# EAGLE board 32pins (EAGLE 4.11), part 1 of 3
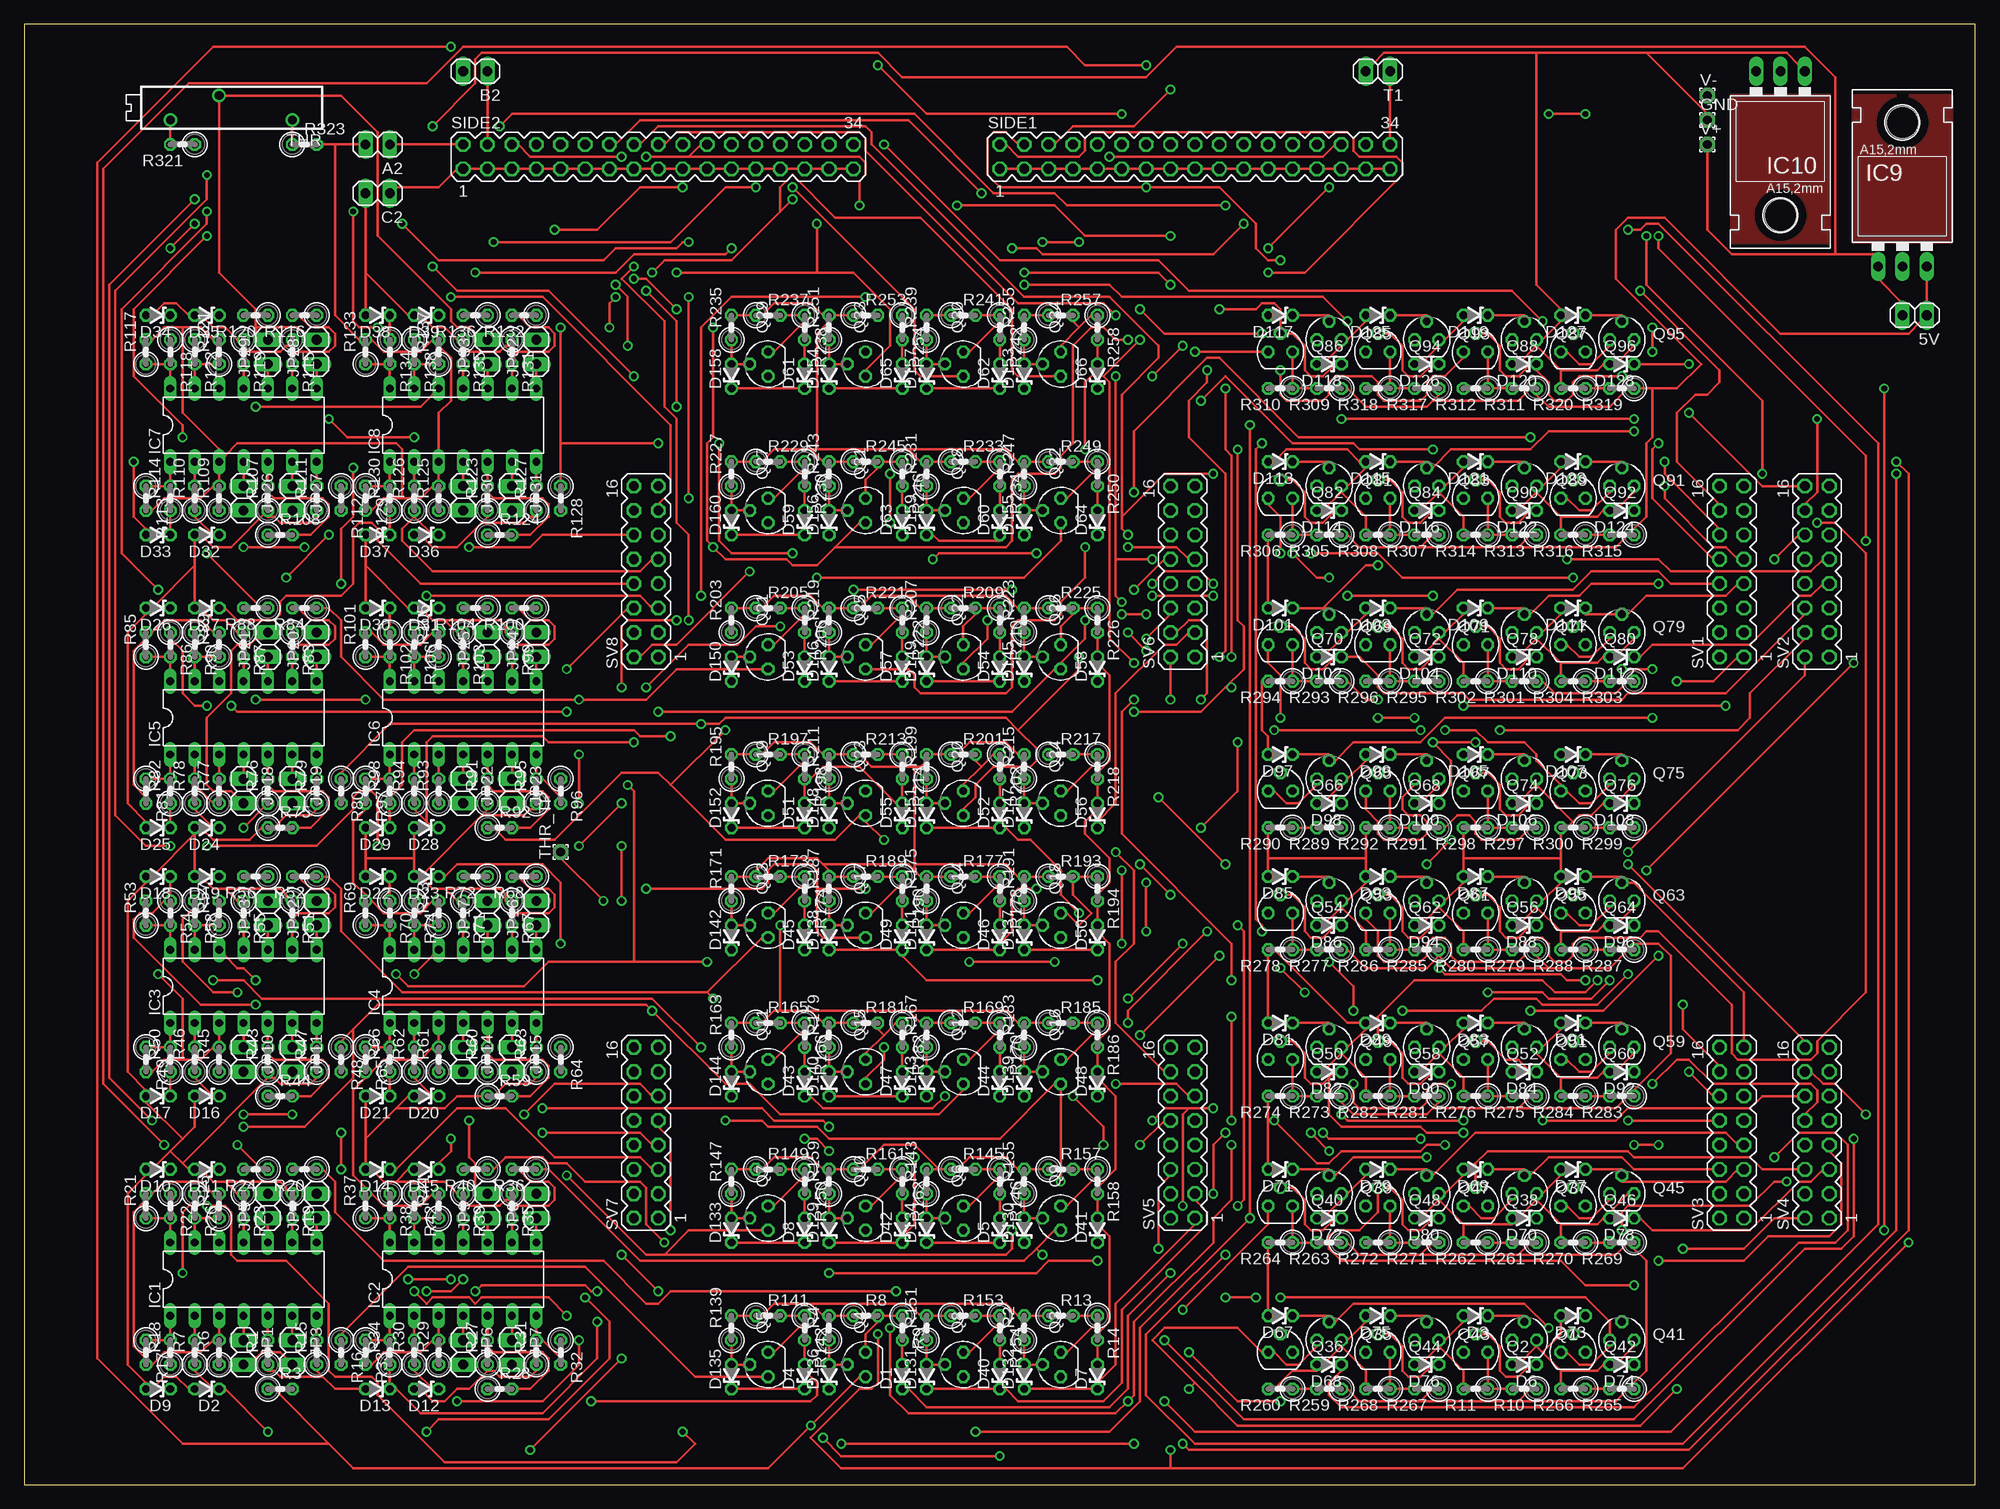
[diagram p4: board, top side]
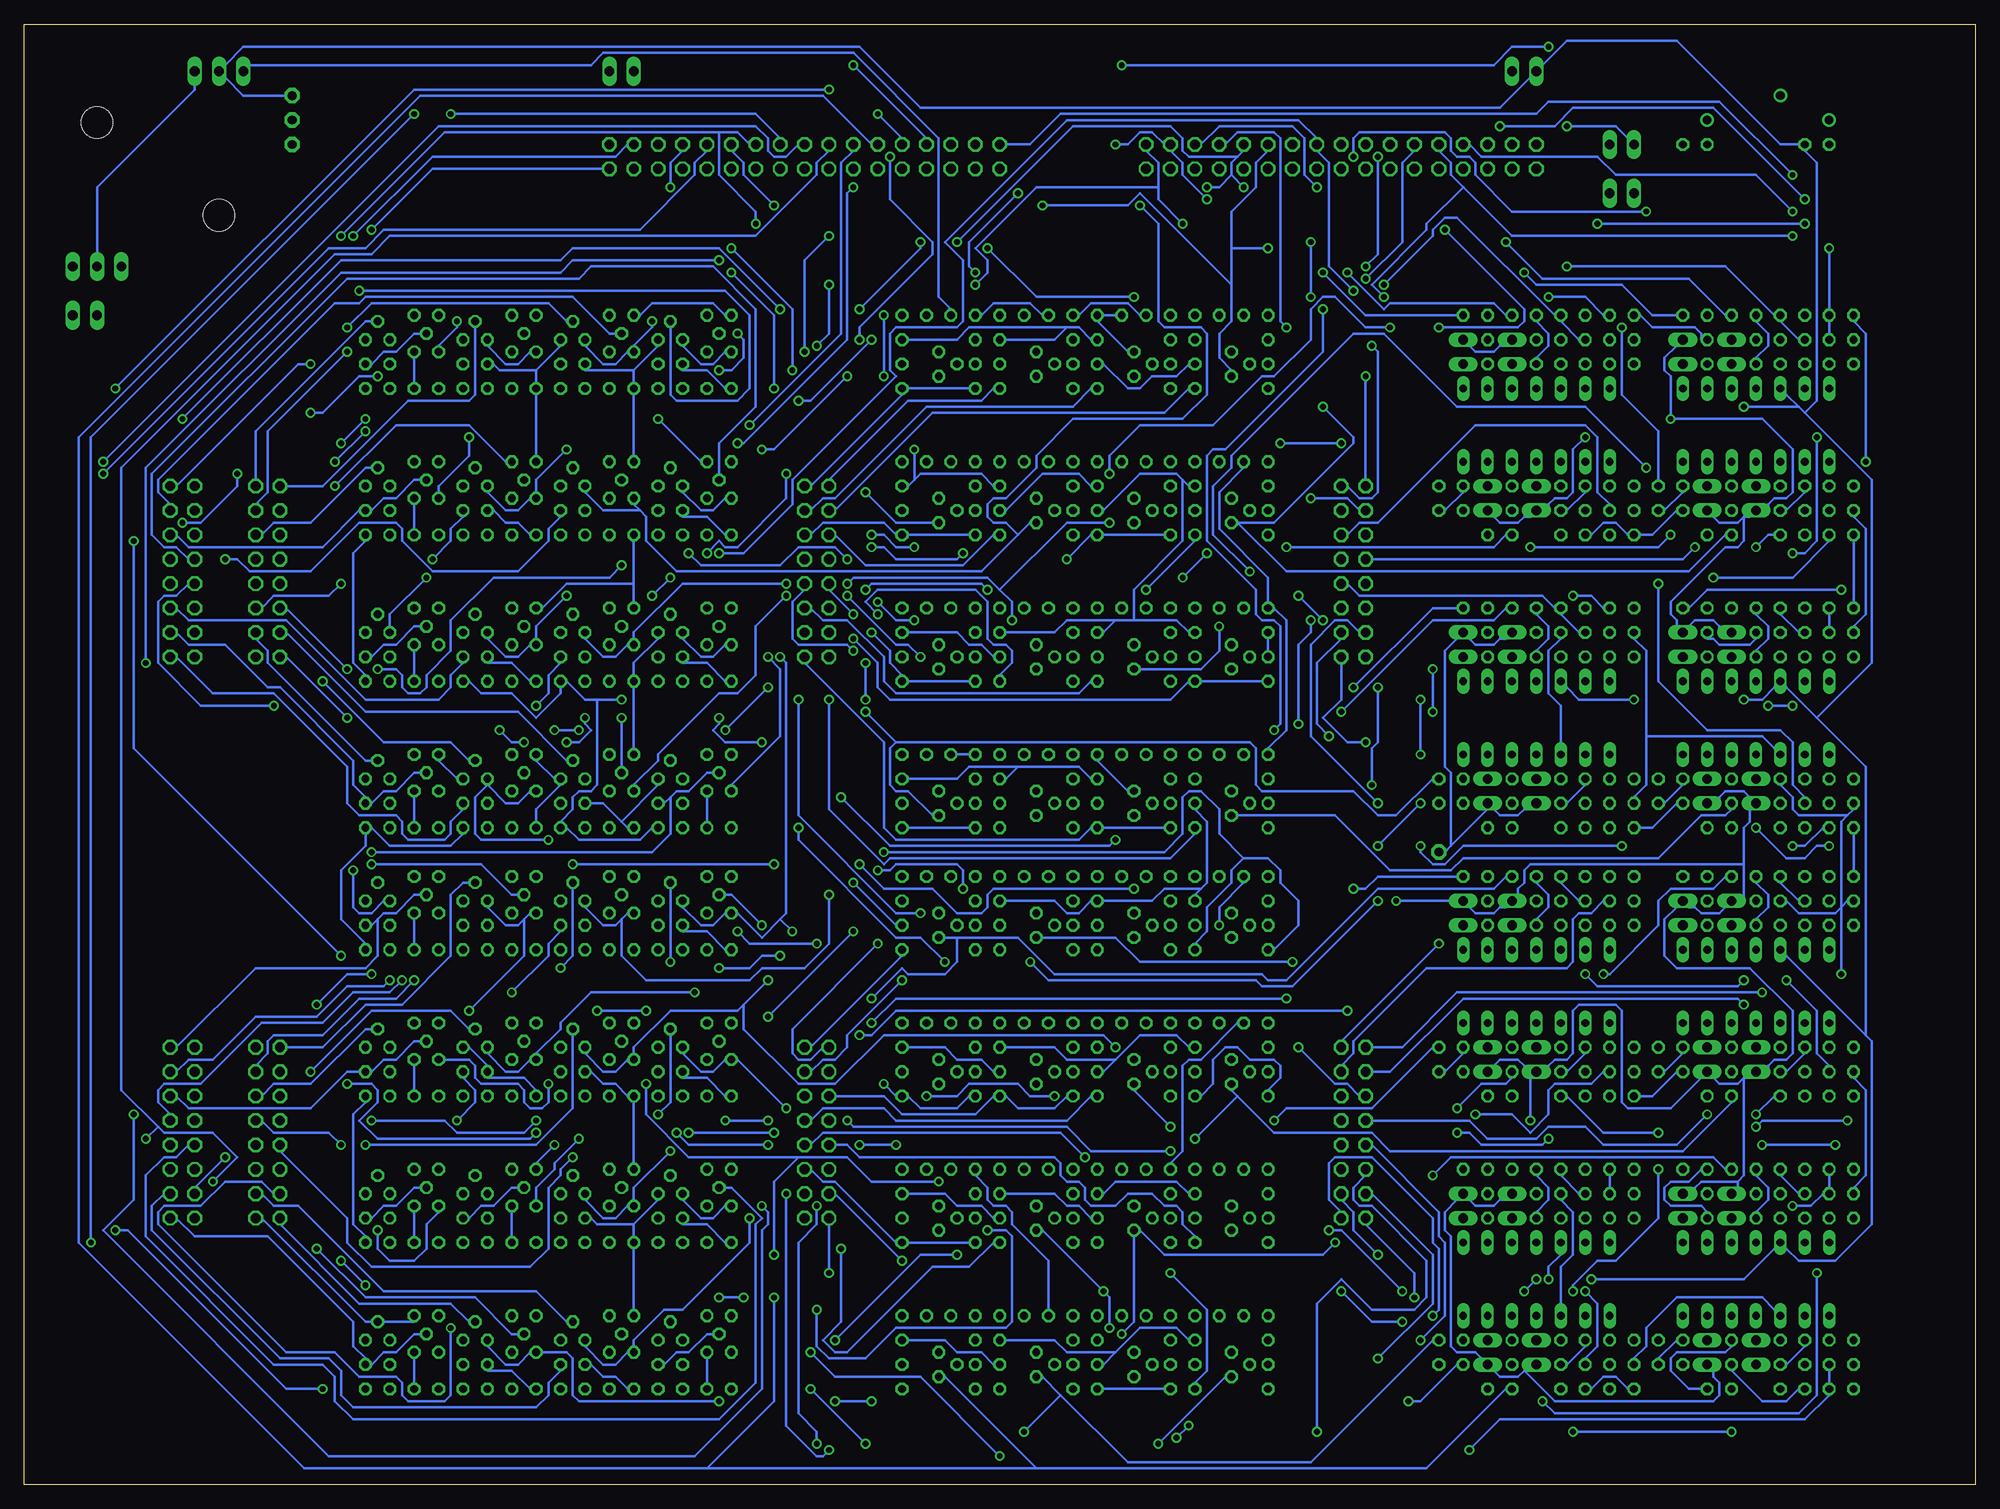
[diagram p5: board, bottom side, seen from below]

Size 203.18 x 152.07 mm. Coordinates in mm from the lower left corner, seen from the top.
Outline: 0,0 203.18,0 203.18,152.07 0,152.07 0,0
Copper layers (1*16): Top 0.035mm / dielectric 1.5mm / Bottom 0.035mm
Design rules "default": minimum track width 10mil, minimum drill 24mil, track to track 8mil, track to pad 8mil, pad to pad 8mil, via to via 8mil, smd to smd 8mil, copper to edge 40mil, drill to drill 8mil, minimum pad ring 10mil, minimum via ring 8mil, stop-mask expansion 4mil, vias tented up to drill 0mil, thermal gap 10mil

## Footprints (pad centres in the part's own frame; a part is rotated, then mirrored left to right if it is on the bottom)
1X02 = drill 1.016 long: 1 -1.27,0; 2 1.27,0
ZDIO-2.5 = drill 0.813 octagon: A 1.27,0; C -1.27,0
1,6/0,9 = drill 0.914 pad 1.6 octagon: 1 0,0
DIL14 = drill 0.813 long: 1 -7.62,-3.81; 2 -5.08,-3.81; 3 -2.54,-3.81; 4 0,-3.81; 5 2.54,-3.81; 6 5.08,-3.81; 7 7.62,-3.81; 8 7.62,3.81; 9 5.08,3.81; 10 2.54,3.81; 11 0,3.81; 12 -2.54,3.81; 13 -5.08,3.81; 14 -7.62,3.81
78XXL = drill 1.016 long: GND 0,-3.81; IN -2.54,-3.81; OUT 2.54,-3.81 | hole 3.302: 0,11.176
79XXL = drill 1.016 long: GND -2.54,-3.81; IN 0,-3.81; OUT 2.54,-3.81 | hole 3.302: 0,11.176
SOT54E = drill 0.813 octagon: D -1.27,0; G 0,1.905; S 1.27,0
0207/2V = drill 0.813 octagon: 1 -1.27,0; 2 1.27,0
MA17-2 = drill 1.016 octagon: 1 -20.32,-1.27; 2 -20.32,1.27; 3 -17.78,-1.27; 4 -17.78,1.27; 5 -15.24,-1.27; 6 -15.24,1.27; 7 -12.7,-1.27; 8 -12.7,1.27; 9 -10.16,-1.27; 10 -10.16,1.27; 11 -7.62,-1.27; 12 -7.62,1.27; 13 -5.08,-1.27; 14 -5.08,1.27; 15 -2.54,-1.27; 16 -2.54,1.27; 17 0,-1.27; 18 0,1.27; 19 2.54,-1.27; 20 2.54,1.27; 21 5.08,-1.27; 22 5.08,1.27; 23 7.62,-1.27; 24 7.62,1.27; 25 10.16,-1.27; 26 10.16,1.27; 27 12.7,-1.27; 28 12.7,1.27; 29 15.24,-1.27; 30 15.24,1.27; 31 17.78,-1.27; 32 17.78,1.27; 33 20.32,-1.27; 34 20.32,1.27
MA08-2 = drill 1.016 octagon: 1 -8.89,-1.27; 2 -8.89,1.27; 3 -6.35,-1.27; 4 -6.35,1.27; 5 -3.81,-1.27; 6 -3.81,1.27; 7 -1.27,-1.27; 8 -1.27,1.27; 9 1.27,-1.27; 10 1.27,1.27; 11 3.81,-1.27; 12 3.81,1.27; 13 6.35,-1.27; 14 6.35,1.27; 15 8.89,-1.27; 16 8.89,1.27
RTRIMT18 = drill 0.9 round: 1 -7.62,1.27; 2 0,-1.27; 3 5.08,1.27

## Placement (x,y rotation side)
5V  [1X02]  196.84,121.75 180 top
A2  [1X02]  36.82,139.53 180 top
B2  [1X02]  46.98,147.16 180 top
C2  [1X02]  36.82,134.46 180 top
D1  1N5229B  [ZDIO-2.5]  91.44,11.27 90 top
D2  1N5229B  [ZDIO-2.5]  19.05,10 180 top
D3  1N5229B  [ZDIO-2.5]  151.12,17.62 180 top
D4  1N5229B  [ZDIO-2.5]  81.28,11.27 90 top
D5  1N5229B  [ZDIO-2.5]  101.59,26.51 90 top
D6  1N5229B  [ZDIO-2.5]  156.21,12.54 180 top
D7  1N5229B  [ZDIO-2.5]  111.76,11.27 90 top
D8  1N5229B  [ZDIO-2.5]  81.28,26.51 90 top
D9  1N5229B  [ZDIO-2.5]  13.96,10 180 top
D10  1N5229B  [ZDIO-2.5]  13.96,32.86 180 top
D11  1N5229B  [ZDIO-2.5]  19.05,32.86 180 top
D12  1N5229B  [ZDIO-2.5]  41.9,10 180 top
D13  1N5229B  [ZDIO-2.5]  36.82,10 180 top
D14  1N5229B  [ZDIO-2.5]  36.82,32.86 180 top
D15  1N5229B  [ZDIO-2.5]  41.9,32.86 180 top
D16  1N5229B  [ZDIO-2.5]  19.05,40.48 180 top
D17  1N5229B  [ZDIO-2.5]  13.96,40.48 180 top
D18  1N5229B  [ZDIO-2.5]  13.96,63.34 180 top
D19  1N5229B  [ZDIO-2.5]  19.05,63.34 180 top
D20  1N5229B  [ZDIO-2.5]  41.9,40.48 180 top
D21  1N5229B  [ZDIO-2.5]  36.82,40.48 180 top
D22  1N5229B  [ZDIO-2.5]  36.82,63.34 180 top
D23  1N5229B  [ZDIO-2.5]  41.9,63.34 180 top
D24  1N5229B  [ZDIO-2.5]  19.05,68.41 180 top
D25  1N5229B  [ZDIO-2.5]  13.96,68.41 180 top
D26  1N5229B  [ZDIO-2.5]  13.96,91.27 180 top
D27  1N5229B  [ZDIO-2.5]  19.05,91.27 180 top
D28  1N5229B  [ZDIO-2.5]  41.9,68.41 180 top
D29  1N5229B  [ZDIO-2.5]  36.82,68.41 180 top
D30  1N5229B  [ZDIO-2.5]  36.82,91.27 180 top
D31  1N5229B  [ZDIO-2.5]  41.9,91.27 180 top
D32  1N5229B  [ZDIO-2.5]  19.05,98.89 180 top
D33  1N5229B  [ZDIO-2.5]  13.96,98.89 180 top
D34  1N5229B  [ZDIO-2.5]  13.96,121.75 180 top
D35  1N5229B  [ZDIO-2.5]  19.05,121.75 180 top
D36  1N5229B  [ZDIO-2.5]  41.9,98.89 180 top
D37  1N5229B  [ZDIO-2.5]  36.82,98.89 180 top
D38  1N5229B  [ZDIO-2.5]  36.82,121.75 180 top
D39  1N5229B  [ZDIO-2.5]  41.9,121.75 180 top
D40  1N5229B  [ZDIO-2.5]  101.59,11.27 90 top
D41  1N5229B  [ZDIO-2.5]  111.76,26.51 90 top
D42  1N5229B  [ZDIO-2.5]  91.44,26.51 90 top
D43  1N5229B  [ZDIO-2.5]  81.28,41.74 90 top
D44  1N5229B  [ZDIO-2.5]  101.59,41.74 90 top
D45  1N5229B  [ZDIO-2.5]  81.28,56.98 90 top
D46  1N5229B  [ZDIO-2.5]  101.59,56.98 90 top
D47  1N5229B  [ZDIO-2.5]  91.44,41.74 90 top
D48  1N5229B  [ZDIO-2.5]  111.76,41.74 90 top
D49  1N5229B  [ZDIO-2.5]  91.44,56.98 90 top
D50  1N5229B  [ZDIO-2.5]  111.76,56.98 90 top
D51  1N5229B  [ZDIO-2.5]  81.28,69.68 90 top
D52  1N5229B  [ZDIO-2.5]  101.59,69.68 90 top
D53  1N5229B  [ZDIO-2.5]  81.28,84.92 90 top
D54  1N5229B  [ZDIO-2.5]  101.59,84.92 90 top
D55  1N5229B  [ZDIO-2.5]  91.44,69.68 90 top
D56  1N5229B  [ZDIO-2.5]  111.76,69.68 90 top
D57  1N5229B  [ZDIO-2.5]  91.44,84.92 90 top
D58  1N5229B  [ZDIO-2.5]  111.76,84.92 90 top
D59  1N5229B  [ZDIO-2.5]  81.28,100.16 90 top
D60  1N5229B  [ZDIO-2.5]  101.59,100.16 90 top
D61  1N5229B  [ZDIO-2.5]  81.28,115.4 90 top
D62  1N5229B  [ZDIO-2.5]  101.59,115.4 90 top
D63  1N5229B  [ZDIO-2.5]  91.44,100.16 90 top
D64  1N5229B  [ZDIO-2.5]  111.76,100.16 90 top
D65  1N5229B  [ZDIO-2.5]  91.44,115.4 90 top
D66  1N5229B  [ZDIO-2.5]  111.76,115.4 90 top
D67  1N5229B  [ZDIO-2.5]  130.81,17.62 180 top
D68  1N5229B  [ZDIO-2.5]  135.88,12.54 180 top
D69  1N5229B  [ZDIO-2.5]  151.12,32.86 180 top
D70  1N5229B  [ZDIO-2.5]  156.21,27.78 180 top
D71  1N5229B  [ZDIO-2.5]  130.81,32.86 180 top
D72  1N5229B  [ZDIO-2.5]  135.88,27.78 180 top
D73  1N5229B  [ZDIO-2.5]  161.28,17.62 180 top
D74  1N5229B  [ZDIO-2.5]  166.37,12.54 180 top
D75  1N5229B  [ZDIO-2.5]  140.97,17.62 180 top
D76  1N5229B  [ZDIO-2.5]  146.05,12.54 180 top
D77  1N5229B  [ZDIO-2.5]  161.28,32.86 180 top
D78  1N5229B  [ZDIO-2.5]  166.37,27.78 180 top
D79  1N5229B  [ZDIO-2.5]  140.97,32.86 180 top
D80  1N5229B  [ZDIO-2.5]  146.05,27.78 180 top
D81  1N5229B  [ZDIO-2.5]  130.81,48.09 180 top
D82  1N5229B  [ZDIO-2.5]  135.88,43.02 180 top
D83  1N5229B  [ZDIO-2.5]  151.12,48.09 180 top
D84  1N5229B  [ZDIO-2.5]  156.21,43.02 180 top
D85  1N5229B  [ZDIO-2.5]  130.81,63.34 180 top
D86  1N5229B  [ZDIO-2.5]  135.88,58.26 180 top
D87  1N5229B  [ZDIO-2.5]  151.12,63.34 180 top
D88  1N5229B  [ZDIO-2.5]  156.21,58.26 180 top
D89  1N5229B  [ZDIO-2.5]  140.97,48.09 180 top
D90  1N5229B  [ZDIO-2.5]  146.05,43.02 180 top
D91  1N5229B  [ZDIO-2.5]  161.28,48.09 180 top
D92  1N5229B  [ZDIO-2.5]  166.37,43.02 180 top
D93  1N5229B  [ZDIO-2.5]  140.97,63.34 180 top
D94  1N5229B  [ZDIO-2.5]  146.05,58.26 180 top
D95  1N5229B  [ZDIO-2.5]  161.28,63.34 180 top
D96  1N5229B  [ZDIO-2.5]  166.37,58.26 180 top
D97  1N5229B  [ZDIO-2.5]  130.81,76.03 180 top
D98  1N5229B  [ZDIO-2.5]  135.88,70.95 180 top
D99  1N5229B  [ZDIO-2.5]  140.97,76.03 180 top
D100  1N5229B  [ZDIO-2.5]  146.05,70.95 180 top
D101  1N5229B  [ZDIO-2.5]  130.81,91.27 180 top
D102  1N5229B  [ZDIO-2.5]  135.88,86.19 180 top
D103  1N5229B  [ZDIO-2.5]  140.97,91.27 180 top
D104  1N5229B  [ZDIO-2.5]  146.05,86.19 180 top
D105  1N5229B  [ZDIO-2.5]  151.12,76.03 180 top
D106  1N5229B  [ZDIO-2.5]  156.21,70.95 180 top
D107  1N5229B  [ZDIO-2.5]  161.28,76.03 180 top
D108  1N5229B  [ZDIO-2.5]  166.37,70.95 180 top
D109  1N5229B  [ZDIO-2.5]  151.12,91.27 180 top
D110  1N5229B  [ZDIO-2.5]  156.21,86.19 180 top
D111  1N5229B  [ZDIO-2.5]  161.28,91.27 180 top
D112  1N5229B  [ZDIO-2.5]  166.37,86.19 180 top
D113  1N5229B  [ZDIO-2.5]  130.81,106.52 180 top
D114  1N5229B  [ZDIO-2.5]  135.88,101.43 180 top
D115  1N5229B  [ZDIO-2.5]  140.97,106.52 180 top
D116  1N5229B  [ZDIO-2.5]  146.05,101.43 180 top
D117  1N5229B  [ZDIO-2.5]  130.81,121.75 180 top
D118  1N5229B  [ZDIO-2.5]  135.88,116.67 180 top
D119  1N5229B  [ZDIO-2.5]  151.12,121.75 180 top
D120  1N5229B  [ZDIO-2.5]  156.21,116.67 180 top
D121  1N5229B  [ZDIO-2.5]  151.12,106.52 180 top
D122  1N5229B  [ZDIO-2.5]  156.21,101.43 180 top
D123  1N5229B  [ZDIO-2.5]  161.28,106.52 180 top
D124  1N5229B  [ZDIO-2.5]  166.37,101.43 180 top
D125  1N5229B  [ZDIO-2.5]  140.97,121.75 180 top
D126  1N5229B  [ZDIO-2.5]  146.05,116.67 180 top
D127  1N5229B  [ZDIO-2.5]  161.28,121.75 180 top
D128  1N5229B  [ZDIO-2.5]  166.37,116.67 180 top
D129  1N5225/3V  [ZDIO-2.5]  83.81,26.51 90 top
D130  1N5225/3V  [ZDIO-2.5]  104.14,26.51 90 top
D131  1N5225/3V  [ZDIO-2.5]  93.98,11.27 90 top
D132  1N5225/3V  [ZDIO-2.5]  104.14,11.27 90 top
D133  1N5225/3V  [ZDIO-2.5]  73.66,26.51 90 top
D134  1N5225/3V  [ZDIO-2.5]  93.98,26.51 90 top
D135  1N5225/3V  [ZDIO-2.5]  73.66,11.27 90 top
D136  1N5225/3V  [ZDIO-2.5]  83.81,11.27 90 top
D137  1N5225/3V  [ZDIO-2.5]  104.14,56.98 90 top
D138  1N5225/3V  [ZDIO-2.5]  83.81,56.98 90 top
D139  1N5225/3V  [ZDIO-2.5]  104.14,41.74 90 top
D140  1N5225/3V  [ZDIO-2.5]  83.81,41.74 90 top
D141  1N5225/3V  [ZDIO-2.5]  93.98,56.98 90 top
D142  1N5225/3V  [ZDIO-2.5]  73.66,56.98 90 top
D143  1N5225/3V  [ZDIO-2.5]  93.98,41.74 90 top
D144  1N5225/3V  [ZDIO-2.5]  73.66,41.74 90 top
D145  1N5225/3V  [ZDIO-2.5]  104.14,84.92 90 top
D146  1N5225/3V  [ZDIO-2.5]  83.81,84.92 90 top
D147  1N5225/3V  [ZDIO-2.5]  104.14,69.68 90 top
D148  1N5225/3V  [ZDIO-2.5]  83.81,69.68 90 top
D149  1N5225/3V  [ZDIO-2.5]  93.98,84.92 90 top
D150  1N5225/3V  [ZDIO-2.5]  73.66,84.92 90 top
D151  1N5225/3V  [ZDIO-2.5]  93.98,69.68 90 top
D152  1N5225/3V  [ZDIO-2.5]  73.66,69.68 90 top
D153  1N5225/3V  [ZDIO-2.5]  104.14,115.4 90 top
D154  1N5225/3V  [ZDIO-2.5]  83.81,115.4 90 top
D155  1N5225/3V  [ZDIO-2.5]  104.14,100.16 90 top
D156  1N5225/3V  [ZDIO-2.5]  83.81,100.16 90 top
D157  1N5225/3V  [ZDIO-2.5]  93.98,115.4 90 top
D158  1N5225/3V  [ZDIO-2.5]  73.66,115.4 90 top
D159  1N5225/3V  [ZDIO-2.5]  93.98,100.16 90 top
D160  1N5225/3V  [ZDIO-2.5]  73.66,100.16 90 top
GND  [1,6/0,9]  175.25,142.08 0 top
IC1  LM139N  [DIL14]  22.86,21.43 0 top
IC2  LM139N  [DIL14]  45.71,21.43 0 top
IC3  LM139N  [DIL14]  22.86,51.91 0 top
IC4  LM139N  [DIL14]  45.71,51.91 0 top
IC5  LM139N  [DIL14]  22.86,79.84 0 top
IC6  LM139N  [DIL14]  45.71,79.84 0 top
IC7  LM139N  [DIL14]  22.86,110.32 0 top
IC8  LM139N  [DIL14]  45.71,110.32 0 top
IC9  [78XXL]  195.58,130.65 0 top
IC10  [79XXL]  182.88,143.34 180 top
JP1  [1X02]  22.86,13.81 270 top
JP3  [1X02]  27.94,13.81 270 top
JP4  [1X02]  30.48,29.05 90 top
JP5  [1X02]  25.39,29.05 90 top
JP6  [1X02]  45.71,13.81 270 top
JP7  [1X02]  50.79,13.81 270 top
JP8  [1X02]  53.34,29.05 90 top
JP9  [1X02]  48.25,29.05 90 top
JP10  [1X02]  22.86,44.29 270 top
JP11  [1X02]  27.94,44.29 270 top
JP12  [1X02]  30.48,59.52 90 top
JP13  [1X02]  25.39,59.52 90 top
JP14  [1X02]  45.71,44.29 270 top
JP15  [1X02]  50.79,44.29 270 top
JP16  [1X02]  53.34,59.52 90 top
JP17  [1X02]  48.25,59.52 90 top
JP18  [1X02]  22.86,72.22 270 top
JP19  [1X02]  27.94,72.22 270 top
JP20  [1X02]  30.48,87.46 90 top
JP21  [1X02]  25.39,87.46 90 top
JP22  [1X02]  45.71,72.22 270 top
JP23  [1X02]  50.79,72.22 270 top
JP24  [1X02]  53.34,87.46 90 top
JP25  [1X02]  48.25,87.46 90 top
JP26  [1X02]  22.86,102.7 270 top
JP27  [1X02]  27.94,102.7 270 top
JP28  [1X02]  30.48,117.94 90 top
JP29  [1X02]  25.39,117.94 90 top
JP30  [1X02]  45.71,102.7 270 top
JP31  [1X02]  50.79,102.7 270 top
JP32  [1X02]  53.34,117.94 90 top
JP33  [1X02]  48.25,117.94 90 top
Q1  BS170  [SOT54E]  156.21,15.08 0 top
Q2  BS250  [SOT54E]  151.12,13.81 0 top
Q3  BS170  [SOT54E]  107.95,12.54 90 top
Q4  BS170  [SOT54E]  87.62,12.54 90 top
Q5  BS170  [SOT54E]  77.47,12.54 90 top
Q6  BS170  [SOT54E]  97.79,27.78 90 top
Q7  BS170  [SOT54E]  77.47,27.78 90 top
Q8  BS170  [SOT54E]  97.79,12.54 90 top
Q9  BS170  [SOT54E]  107.95,27.78 90 top
Q10  BS170  [SOT54E]  87.62,27.78 90 top
Q11  BS170  [SOT54E]  77.47,43.02 90 top
Q12  BS170  [SOT54E]  97.79,43.02 90 top
Q13  BS170  [SOT54E]  77.47,58.26 90 top
Q14  BS170  [SOT54E]  97.79,58.26 90 top
Q15  BS170  [SOT54E]  87.62,43.02 90 top
Q16  BS170  [SOT54E]  107.95,43.02 90 top
Q17  BS170  [SOT54E]  87.62,58.26 90 top
Q18  BS170  [SOT54E]  107.95,58.26 90 top
Q19  BS170  [SOT54E]  77.47,70.95 90 top
Q20  BS170  [SOT54E]  97.79,70.95 90 top
Q21  BS170  [SOT54E]  77.47,86.19 90 top
Q22  BS170  [SOT54E]  97.79,86.19 90 top
Q23  BS170  [SOT54E]  87.62,70.95 90 top
Q24  BS170  [SOT54E]  107.95,70.95 90 top
Q25  BS170  [SOT54E]  87.62,86.19 90 top
Q26  BS170  [SOT54E]  107.95,86.19 90 top
Q27  BS170  [SOT54E]  77.47,101.43 90 top
Q28  BS170  [SOT54E]  97.79,101.43 90 top
Q29  BS170  [SOT54E]  77.47,116.67 90 top
Q30  BS170  [SOT54E]  97.79,116.67 90 top
Q31  BS170  [SOT54E]  87.62,101.43 90 top
Q32  BS170  [SOT54E]  107.95,101.43 90 top
Q33  BS170  [SOT54E]  87.62,116.67 90 top
Q34  BS170  [SOT54E]  107.95,116.67 90 top
Q35  BS170  [SOT54E]  135.88,15.08 0 top
Q36  BS250  [SOT54E]  130.81,13.81 0 top
Q37  BS170  [SOT54E]  156.21,30.32 0 top
Q38  BS250  [SOT54E]  151.12,29.05 0 top
Q39  BS170  [SOT54E]  135.88,30.32 0 top
Q40  BS250  [SOT54E]  130.81,29.05 0 top
Q41  BS170  [SOT54E]  166.37,15.08 0 top
Q42  BS250  [SOT54E]  161.28,13.81 0 top
Q43  BS170  [SOT54E]  146.05,15.08 0 top
Q44  BS250  [SOT54E]  140.97,13.81 0 top
Q45  BS170  [SOT54E]  166.37,30.32 0 top
Q46  BS250  [SOT54E]  161.28,29.05 0 top
Q47  BS170  [SOT54E]  146.05,30.32 0 top
Q48  BS250  [SOT54E]  140.97,29.05 0 top
Q49  BS170  [SOT54E]  135.88,45.55 0 top
Q50  BS250  [SOT54E]  130.81,44.29 0 top
Q51  BS170  [SOT54E]  156.21,45.55 0 top
Q52  BS250  [SOT54E]  151.12,44.29 0 top
Q53  BS170  [SOT54E]  135.88,60.8 0 top
Q54  BS250  [SOT54E]  130.81,59.52 0 top
Q55  BS170  [SOT54E]  156.21,60.8 0 top
Q56  BS250  [SOT54E]  151.12,59.52 0 top
Q57  BS170  [SOT54E]  146.05,45.55 0 top
Q58  BS250  [SOT54E]  140.97,44.29 0 top
Q59  BS170  [SOT54E]  166.37,45.55 0 top
Q60  BS250  [SOT54E]  161.28,44.29 0 top
Q61  BS170  [SOT54E]  146.05,60.8 0 top
Q62  BS250  [SOT54E]  140.97,59.52 0 top
Q63  BS170  [SOT54E]  166.37,60.8 0 top
Q64  BS250  [SOT54E]  161.28,59.52 0 top
Q65  BS170  [SOT54E]  135.88,73.49 0 top
Q66  BS250  [SOT54E]  130.81,72.22 0 top
Q67  BS170  [SOT54E]  146.05,73.49 0 top
Q68  BS250  [SOT54E]  140.97,72.22 0 top
Q69  BS170  [SOT54E]  135.88,88.73 0 top
Q70  BS250  [SOT54E]  130.81,87.46 0 top
Q71  BS170  [SOT54E]  146.05,88.73 0 top
Q72  BS250  [SOT54E]  140.97,87.46 0 top
Q73  BS170  [SOT54E]  156.21,73.49 0 top
Q74  BS250  [SOT54E]  151.12,72.22 0 top
Q75  BS170  [SOT54E]  166.37,73.49 0 top
Q76  BS250  [SOT54E]  161.28,72.22 0 top
Q77  BS170  [SOT54E]  156.21,88.73 0 top
Q78  BS250  [SOT54E]  151.12,87.46 0 top
Q79  BS170  [SOT54E]  166.37,88.73 0 top
Q80  BS250  [SOT54E]  161.28,87.46 0 top
Q81  BS170  [SOT54E]  135.88,103.97 0 top
Q82  BS250  [SOT54E]  130.81,102.7 0 top
Q83  BS170  [SOT54E]  146.05,103.97 0 top
Q84  BS250  [SOT54E]  140.97,102.7 0 top
Q85  BS170  [SOT54E]  135.88,119.21 0 top
Q86  BS250  [SOT54E]  130.81,117.94 0 top
Q87  BS170  [SOT54E]  156.21,119.21 0 top
Q88  BS250  [SOT54E]  151.12,117.94 0 top
Q89  BS170  [SOT54E]  156.21,103.97 0 top
Q90  BS250  [SOT54E]  151.12,102.7 0 top
Q91  BS170  [SOT54E]  166.37,103.97 0 top
Q92  BS250  [SOT54E]  161.28,102.7 0 top
Q93  BS170  [SOT54E]  146.05,119.21 0 top
Q94  BS250  [SOT54E]  140.97,117.94 0 top
Q95  BS170  [SOT54E]  166.37,119.21 0 top
Q96  BS250  [SOT54E]  161.28,117.94 0 top
R1  27K  [0207/2V]  25.39,13.81 90 top
R2  5K  [0207/2V]  104.14,16.35 90 top
R3  75K  [0207/2V]  26.67,10 0 top
R4  5K  [0207/2V]  83.81,16.35 90 top
R6  5K  [0207/2V]  20.32,13.81 90 top
R7  5K  [0207/2V]  17.78,13.81 90 top
R8  5K  [0207/2V]  87.62,17.62 0 top
R9  10K  [0207/2V]  91.44,16.35 270 top
R10  5K  [0207/2V]  156.21,10 180 top
R11  10K  [0207/2V]  151.12,10 180 top
R13  5K  [0207/2V]  107.95,17.62 0 top
R14  10K  [0207/2V]  111.76,16.35 270 top
R15  27K  [0207/2V]  30.48,13.81 90 top
R16  75K  [0207/2V]  33.02,13.81 270 top
R17  5K  [0207/2V]  12.69,13.81 270 top
R18  5K  [0207/2V]  15.23,13.81 90 top
R19  27K  [0207/2V]  27.94,29.05 270 top
R20  75K  [0207/2V]  29.21,32.86 180 top
R21  5K  [0207/2V]  12.69,29.05 90 top
R22  5K  [0207/2V]  15.23,29.05 270 top
R23  27K  [0207/2V]  22.86,29.05 270 top
R24  75K  [0207/2V]  24.12,32.86 180 top
R25  5K  [0207/2V]  20.32,29.05 90 top
R26  5K  [0207/2V]  17.78,29.05 270 top
R27  27K  [0207/2V]  48.25,13.81 90 top
R28  75K  [0207/2V]  49.52,10 0 top
R29  5K  [0207/2V]  43.17,13.81 90 top
R30  5K  [0207/2V]  40.63,13.81 90 top
R31  27K  [0207/2V]  53.34,13.81 90 top
R32  75K  [0207/2V]  55.88,13.81 270 top
R33  5K  [0207/2V]  35.55,13.81 270 top
R34  5K  [0207/2V]  38.09,13.81 90 top
R35  27K  [0207/2V]  50.79,29.05 270 top
R36  75K  [0207/2V]  52.06,32.86 180 top
R37  5K  [0207/2V]  35.55,29.05 90 top
R38  5K  [0207/2V]  38.09,29.05 270 top
R39  27K  [0207/2V]  45.71,29.05 270 top
R40  75K  [0207/2V]  46.98,32.86 180 top
R41  5K  [0207/2V]  43.17,29.05 90 top
R42  5K  [0207/2V]  40.63,29.05 270 top
R43  27K  [0207/2V]  25.39,44.29 90 top
R44  75K  [0207/2V]  26.67,40.48 0 top
R45  5K  [0207/2V]  20.32,44.29 90 top
R46  5K  [0207/2V]  17.78,44.29 90 top
R47  27K  [0207/2V]  30.48,44.29 90 top
R48  75K  [0207/2V]  33.02,44.29 270 top
R49  5K  [0207/2V]  12.69,44.29 270 top
R50  5K  [0207/2V]  15.23,44.29 90 top
R51  27K  [0207/2V]  27.94,59.52 270 top
R52  75K  [0207/2V]  29.21,63.34 180 top
R53  5K  [0207/2V]  12.69,59.52 90 top
R54  5K  [0207/2V]  15.23,59.52 270 top
R55  27K  [0207/2V]  22.86,59.52 270 top
R56  75K  [0207/2V]  24.12,63.34 180 top
R57  5K  [0207/2V]  20.32,59.52 90 top
R58  5K  [0207/2V]  17.78,59.52 270 top
R59  27K  [0207/2V]  49.52,40.48 0 top
R60  75K  [0207/2V]  48.25,44.29 90 top
R61  5K  [0207/2V]  43.17,44.29 90 top
R62  5K  [0207/2V]  40.63,44.29 90 top
R63  27K  [0207/2V]  53.34,44.29 90 top
R64  75K  [0207/2V]  55.88,44.29 270 top
R65  5K  [0207/2V]  35.55,44.29 270 top
R66  5K  [0207/2V]  38.09,44.29 90 top
R67  27K  [0207/2V]  50.79,59.52 270 top
R68  75K  [0207/2V]  52.06,63.34 180 top
R69  5K  [0207/2V]  35.55,59.52 90 top
R70  5K  [0207/2V]  38.09,59.52 270 top
R71  27K  [0207/2V]  45.71,59.52 270 top
R72  75K  [0207/2V]  46.98,63.34 180 top
R73  5K  [0207/2V]  43.17,59.52 90 top
R74  5K  [0207/2V]  40.63,59.52 270 top
R75  27K  [0207/2V]  26.67,68.41 0 top
R76  75K  [0207/2V]  25.39,72.22 90 top
R77  5K  [0207/2V]  20.32,72.22 90 top
R78  5K  [0207/2V]  17.78,72.22 90 top
R79  27K  [0207/2V]  30.48,72.22 90 top
R80  75K  [0207/2V]  33.02,72.22 270 top
R81  5K  [0207/2V]  12.69,72.22 270 top
R82  5K  [0207/2V]  15.23,72.22 90 top
R83  27K  [0207/2V]  27.94,87.46 270 top
R84  75K  [0207/2V]  29.21,91.27 180 top
R85  5K  [0207/2V]  12.69,87.46 90 top
R86  5K  [0207/2V]  15.23,87.46 270 top
R87  27K  [0207/2V]  22.86,87.46 270 top
R88  75K  [0207/2V]  24.12,91.27 180 top
R89  5K  [0207/2V]  20.32,87.46 90 top
R90  5K  [0207/2V]  17.78,87.46 270 top
R91  27K  [0207/2V]  48.25,72.22 90 top
R92  75K  [0207/2V]  49.52,68.41 0 top
R93  5K  [0207/2V]  43.17,72.22 90 top
R94  5K  [0207/2V]  40.63,72.22 90 top
R95  27K  [0207/2V]  53.34,72.22 90 top
R96  75K  [0207/2V]  55.88,72.22 270 top
R97  5K  [0207/2V]  35.55,72.22 270 top
R98  5K  [0207/2V]  38.09,72.22 90 top
R99  27K  [0207/2V]  50.79,87.46 270 top
R100  75K  [0207/2V]  52.06,91.27 180 top
R101  5K  [0207/2V]  35.55,87.46 90 top
R102  5K  [0207/2V]  38.09,87.46 270 top
R103  27K  [0207/2V]  45.71,87.46 270 top
R104  75K  [0207/2V]  46.98,91.27 180 top
R105  5K  [0207/2V]  43.17,87.46 90 top
R106  5K  [0207/2V]  40.63,87.46 270 top
R107  27K  [0207/2V]  25.39,102.7 90 top
R108  75K  [0207/2V]  26.67,98.89 0 top
R109  5K  [0207/2V]  20.32,102.7 90 top
R110  5K  [0207/2V]  17.78,102.7 90 top
R111  27K  [0207/2V]  30.48,102.7 90 top
R112  75K  [0207/2V]  33.02,102.7 270 top
R113  5K  [0207/2V]  12.69,102.7 270 top
R114  5K  [0207/2V]  15.23,102.7 90 top
R115  27K  [0207/2V]  27.94,117.94 270 top
R116  75K  [0207/2V]  29.21,121.75 180 top
R117  5K  [0207/2V]  12.69,117.94 90 top
R118  5K  [0207/2V]  15.23,117.94 270 top
R119  27K  [0207/2V]  22.86,117.94 270 top
R120  75K  [0207/2V]  24.12,121.75 180 top
R121  5K  [0207/2V]  20.32,117.94 90 top
R122  5K  [0207/2V]  17.78,117.94 270 top
R123  27K  [0207/2V]  48.25,102.7 90 top
R124  75K  [0207/2V]  49.52,98.89 0 top
R125  5K  [0207/2V]  43.17,102.7 90 top
R126  5K  [0207/2V]  40.63,102.7 90 top
R127  27K  [0207/2V]  53.34,102.7 90 top
R128  75K  [0207/2V]  55.88,102.7 270 top
R129  5K  [0207/2V]  35.55,102.7 270 top
R130  5K  [0207/2V]  38.09,102.7 90 top
R131  27K  [0207/2V]  50.79,117.94 270 top
R132  75K  [0207/2V]  52.06,121.75 180 top
R133  5K  [0207/2V]  35.55,117.94 90 top
R134  5K  [0207/2V]  38.09,117.94 270 top
R135  27K  [0207/2V]  45.71,117.94 270 top
R136  75K  [0207/2V]  46.98,121.75 180 top
R137  5K  [0207/2V]  43.17,117.94 90 top
R138  5K  [0207/2V]  40.63,117.94 270 top
R139  5K  [0207/2V]  73.66,16.35 90 top
R141  5K  [0207/2V]  77.47,17.62 0 top
R142  10K  [0207/2V]  81.28,16.35 270 top
R143  5K  [0207/2V]  93.98,31.59 90 top
R145  5K  [0207/2V]  97.79,32.86 0 top
R146  10K  [0207/2V]  101.59,31.59 270 top
R147  5K  [0207/2V]  73.66,31.59 90 top
R149  5K  [0207/2V]  77.47,32.86 0 top
R150  10K  [0207/2V]  81.28,31.59 270 top
R151  5K  [0207/2V]  93.98,16.35 90 top
R153  5K  [0207/2V]  97.79,17.62 0 top
R154  10K  [0207/2V]  101.59,16.35 270 top
R155  5K  [0207/2V]  104.14,31.59 90 top
R157  5K  [0207/2V]  107.95,32.86 0 top
R158  10K  [0207/2V]  111.76,31.59 270 top
R159  5K  [0207/2V]  83.81,31.59 90 top
R161  5K  [0207/2V]  87.62,32.86 0 top
R162  10K  [0207/2V]  91.44,31.59 270 top
R163  5K  [0207/2V]  73.66,46.83 90 top
R165  5K  [0207/2V]  77.47,48.09 0 top
R166  10K  [0207/2V]  81.28,46.83 270 top
R167  5K  [0207/2V]  93.98,46.83 90 top
R169  5K  [0207/2V]  97.79,48.09 0 top
R170  10K  [0207/2V]  101.59,46.83 270 top
R171  5K  [0207/2V]  73.66,62.06 90 top
R173  5K  [0207/2V]  77.47,63.34 0 top
R174  10K  [0207/2V]  81.28,62.06 270 top
R175  5K  [0207/2V]  93.98,62.06 90 top
R177  5K  [0207/2V]  97.79,63.34 0 top
R178  10K  [0207/2V]  101.59,62.06 270 top
R179  5K  [0207/2V]  83.81,46.83 90 top
R181  5K  [0207/2V]  87.62,48.09 0 top
R182  10K  [0207/2V]  91.44,46.83 270 top
R183  5K  [0207/2V]  104.14,46.83 90 top
R185  5K  [0207/2V]  107.95,48.09 0 top
R186  10K  [0207/2V]  111.76,46.83 270 top
R187  5K  [0207/2V]  83.81,62.06 90 top
R189  5K  [0207/2V]  87.62,63.34 0 top
R190  10K  [0207/2V]  91.44,62.06 270 top
R191  5K  [0207/2V]  104.14,62.06 90 top
R193  5K  [0207/2V]  107.95,63.34 0 top
R194  10K  [0207/2V]  111.76,62.06 270 top
R195  5K  [0207/2V]  73.66,74.77 90 top
R197  5K  [0207/2V]  77.47,76.03 0 top
R198  10K  [0207/2V]  81.28,74.77 270 top
R199  5K  [0207/2V]  93.98,74.77 90 top
R201  5K  [0207/2V]  97.79,76.03 0 top
R202  10K  [0207/2V]  101.59,74.77 270 top
R203  5K  [0207/2V]  73.66,90 90 top
R205  5K  [0207/2V]  77.47,91.27 0 top
R206  10K  [0207/2V]  81.28,90 270 top
R207  5K  [0207/2V]  93.98,90 90 top
R209  5K  [0207/2V]  97.79,91.27 0 top
R210  10K  [0207/2V]  101.59,90 270 top
R211  5K  [0207/2V]  83.81,74.77 90 top
R213  5K  [0207/2V]  87.62,76.03 0 top
R214  10K  [0207/2V]  91.44,74.77 270 top
R215  5K  [0207/2V]  104.14,74.77 90 top
R217  5K  [0207/2V]  107.95,76.03 0 top
R218  10K  [0207/2V]  111.76,74.77 270 top
R219  5K  [0207/2V]  83.81,90 90 top
R221  5K  [0207/2V]  87.62,91.27 0 top
R222  10K  [0207/2V]  91.44,90 270 top
R223  5K  [0207/2V]  104.14,90 90 top
R225  5K  [0207/2V]  107.95,91.27 0 top
R226  10K  [0207/2V]  111.76,90 270 top
R227  5K  [0207/2V]  73.66,105.24 90 top
R229  5K  [0207/2V]  77.47,106.52 0 top
R230  10K  [0207/2V]  81.28,105.24 270 top
R231  5K  [0207/2V]  93.98,105.24 90 top
R233  5K  [0207/2V]  97.79,106.52 0 top
R234  10K  [0207/2V]  101.59,105.24 270 top
R235  5K  [0207/2V]  73.66,120.48 90 top
R237  5K  [0207/2V]  77.47,121.75 0 top
R238  10K  [0207/2V]  81.28,120.48 270 top
R239  5K  [0207/2V]  93.98,120.48 90 top
R241  5K  [0207/2V]  97.79,121.75 0 top
R242  10K  [0207/2V]  101.59,120.48 270 top
R243  5K  [0207/2V]  83.81,105.24 90 top
R245  5K  [0207/2V]  87.62,106.52 0 top
R246  10K  [0207/2V]  91.44,105.24 270 top
R247  5K  [0207/2V]  104.14,105.24 90 top
R249  5K  [0207/2V]  107.95,106.52 0 top
R250  10K  [0207/2V]  111.76,105.24 270 top
R251  5K  [0207/2V]  83.81,120.48 90 top
R253  5K  [0207/2V]  87.62,121.75 0 top
R254  10K  [0207/2V]  91.44,120.48 270 top
R255  5K  [0207/2V]  104.14,120.48 90 top
R257  5K  [0207/2V]  107.95,121.75 0 top
R258  10K  [0207/2V]  111.76,120.48 270 top
R259  5K  [0207/2V]  135.88,10 180 top
R260  10K  [0207/2V]  130.81,10 180 top
R261  5K  [0207/2V]  156.21,25.23 180 top
R262  10K  [0207/2V]  151.12,25.23 180 top
R263  5K  [0207/2V]  135.88,25.23 180 top
R264  10K  [0207/2V]  130.81,25.23 180 top
R265  5K  [0207/2V]  166.37,10 180 top
R266  10K  [0207/2V]  161.28,10 180 top
R267  5K  [0207/2V]  146.05,10 180 top
R268  10K  [0207/2V]  140.97,10 180 top
R269  5K  [0207/2V]  166.37,25.23 180 top
R270  10K  [0207/2V]  161.28,25.23 180 top
R271  5K  [0207/2V]  146.05,25.23 180 top
R272  10K  [0207/2V]  140.97,25.23 180 top
R273  5K  [0207/2V]  135.88,40.48 180 top
R274  10K  [0207/2V]  130.81,40.48 180 top
R275  5K  [0207/2V]  156.21,40.48 180 top
R276  10K  [0207/2V]  151.12,40.48 180 top
R277  5K  [0207/2V]  135.88,55.72 180 top
R278  10K  [0207/2V]  130.81,55.72 180 top
R279  5K  [0207/2V]  156.21,55.72 180 top
R280  10K  [0207/2V]  151.12,55.72 180 top
R281  5K  [0207/2V]  146.05,40.48 180 top
R282  10K  [0207/2V]  140.97,40.48 180 top
R283  5K  [0207/2V]  166.37,40.48 180 top
R284  10K  [0207/2V]  161.28,40.48 180 top
R285  5K  [0207/2V]  146.05,55.72 180 top
R286  10K  [0207/2V]  140.97,55.72 180 top
R287  5K  [0207/2V]  166.37,55.72 180 top
R288  10K  [0207/2V]  161.28,55.72 180 top
R289  5K  [0207/2V]  135.88,68.41 180 top
R290  10K  [0207/2V]  130.81,68.41 180 top
R291  5K  [0207/2V]  146.05,68.41 180 top
R292  10K  [0207/2V]  140.97,68.41 180 top
R293  5K  [0207/2V]  135.88,83.65 180 top
R294  10K  [0207/2V]  130.81,83.65 180 top
R295  5K  [0207/2V]  146.05,83.65 180 top
R296  10K  [0207/2V]  140.97,83.65 180 top
R297  5K  [0207/2V]  156.21,68.41 180 top
R298  10K  [0207/2V]  151.12,68.41 180 top
R299  5K  [0207/2V]  166.37,68.41 180 top
R300  10K  [0207/2V]  161.28,68.41 180 top
R301  5K  [0207/2V]  156.21,83.65 180 top
R302  10K  [0207/2V]  151.12,83.65 180 top
R303  5K  [0207/2V]  166.37,83.65 180 top
R304  10K  [0207/2V]  161.28,83.65 180 top
R305  5K  [0207/2V]  135.88,98.89 180 top
R306  10K  [0207/2V]  130.81,98.89 180 top
R307  5K  [0207/2V]  146.05,98.89 180 top
R308  10K  [0207/2V]  140.97,98.89 180 top
R309  5K  [0207/2V]  135.88,114.13 180 top
R310  10K  [0207/2V]  130.81,114.13 180 top
R311  5K  [0207/2V]  156.21,114.13 180 top
R312  10K  [0207/2V]  151.12,114.13 180 top
R313  5K  [0207/2V]  156.21,98.89 180 top
R314  10K  [0207/2V]  151.12,98.89 180 top
R315  5K  [0207/2V]  166.37,98.89 180 top
R316  10K  [0207/2V]  161.28,98.89 180 top
R317  5K  [0207/2V]  146.05,114.13 180 top
R318  10K  [0207/2V]  140.97,114.13 180 top
R319  5K  [0207/2V]  166.37,114.13 180 top
R320  10K  [0207/2V]  161.28,114.13 180 top
R321  [0207/2V]  16.51,139.53 180 top
R323  [0207/2V]  29.21,139.53 0 top
SIDE1  [MA17-2]  121.92,138.27 0 top
SIDE2  [MA17-2]  66.04,138.27 0 top
SV1  [MA08-2]  177.8,95.08 90 top
SV2  [MA08-2]  186.69,95.08 90 top
SV3  [MA08-2]  177.8,36.66 90 top
SV4  [MA08-2]  186.69,36.66 90 top
SV5  [MA08-2]  120.65,36.66 90 top
SV6  [MA08-2]  120.65,95.08 90 top
SV7  [MA08-2]  64.77,36.66 90 top
SV8  [MA08-2]  64.77,95.08 90 top
T1  [1X02]  140.97,147.16 180 top
THR  [RTRIMT18]  20.32,143.34 180 top
THR_TP  [1,6/0,9]  55.88,65.88 90 top
V+  [1,6/0,9]  175.25,139.53 0 top
V-  [1,6/0,9]  175.25,144.62 0 top

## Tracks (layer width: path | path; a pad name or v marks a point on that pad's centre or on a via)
+5V  (via drill 0.61)
  Top 0.254: IC9.OUT 198.12,125.56 198.12,123.02 5V.1 197.48,121.12 196.21,119.85 182.88,119.85 170.81,131.92 167,131.92 165.73,130.65 165.73,125.56 174.62,116.67 172.08,114.13 169.54,114.13 | 146.68,112.86 147.31,113.5 R317.1 | 146.68,112.86 146.05,112.23 139.69,112.23 137.79,114.13 R309.1 | 146.68,112.86 155.57,112.86 156.84,114.13 R311.1 157.47,113.5 158.75,112.23 165.09,112.23 167,114.13 R319.1 168.27,114.13 169.54,114.13 | 146.68,39.2 147.31,39.84 R281.1 | 146.68,39.2 146.05,38.57 138.43,38.57 137.16,39.84 R273.1 | 155.57,39.2 156.84,40.48 R275.1 | 155.57,39.2 146.68,39.2 | 155.57,39.2 165.73,39.2 167,40.48 R283.1 167.63,41.11 171.44,44.92 171.44,55.08 170.18,56.35 167.63,56.35 R287.1 167,55.72 165.09,53.81 158.75,53.81 | 145.41,8.73 139.06,8.73 137.79,10 R259.1 | 145.41,8.73 146.68,10 R267.1 | 155.57,8.73 156.84,10 R10.1 | 155.57,8.73 145.41,8.73 | 155.57,8.73 165.73,8.73 167,10 R265.1 167.63,10.63 168.91,11.9 168.91,23.33 167.63,24.6 R269.1 167,25.23 165.73,23.96 155.57,23.96 | 145.41,23.96 139.06,23.96 137.79,25.23 R263.1 | 145.41,23.96 146.68,25.23 R271.1 | 155.57,23.96 156.84,25.23 R261.1 | 155.57,23.96 145.41,23.96 | 147.31,55.08 146.05,53.81 139.69,53.81 137.79,55.72 R277.1 | 147.31,55.08 R285.1 147.31,55.08 | 158.75,53.81 157.47,55.08 R279.1 | 147.31,55.08 148.59,53.81 158.75,53.81 | v140.97,81.75 139.69,81.75 137.79,83.65 R293.1 | R301.1 158.11,83.65 159.38,82.38 165.73,82.38 167,83.65 R303.1 | 145.41,97.62 139.06,97.62 137.79,98.89 R305.1 | 145.41,97.62 146.68,98.89 R307.1 | 155.57,97.62 156.84,98.89 R313.1 | 155.57,97.62 145.41,97.62 | 155.57,97.62 165.73,97.62 167,98.89 R315.1 167.63,99.53 168.91,100.8 168.91,108.42 169.54,109.05 169.54,114.13
  Top 0.254: R297.1 156.84,68.41 155.57,67.14 151.76,67.14 151.12,67.78 151.12,69.05 150.49,69.68 149.22,69.68 147.95,68.41 R291.1
  Bottom 0.254: R283.1 167.63,39.84 168.91,38.57 168.91,27.14 167.63,25.87 R269.1 | R297.1 157.47,67.78 158.75,66.51 165.09,66.51 167,68.41 R299.1 167.63,67.78 167.63,66.51 170.18,63.97 170.18,58.89 167.63,56.35 R287.1 | R289.1 137.79,68.41 139.06,67.14 145.41,67.14 146.68,68.41 R291.1 147.31,69.05 146.05,70.32 146.05,71.59 145.41,72.22 144.14,72.22 143.5,72.86 143.5,81.75 | 143.5,81.75 144.78,81.75 146.68,83.65 R295.1 147.31,83.02 147.31,82.38 149.86,79.84 152.4,82.38 155.57,82.38 156.84,83.65 R301.1 | 143.5,81.75 v140.97,81.75 | R303.1 167.63,84.29 168.91,85.56 168.91,96.99 167.63,98.26 R315.1
-5V  (via drill 0.61)
  Top 0.254: R185.1 106.04,48.09 104.77,48.09 R183.2 103.5,48.09 102.23,49.37 92.07,49.37 | R169.1 95.88,48.09 94.61,48.09 R167.2 93.34,48.09 92.07,49.37 | R163.2 74.29,48.09 75.56,48.09 R165.1 76.83,48.09 78.1,49.37 78.73,49.37 | R181.1 85.72,48.09 84.45,48.09 R179.2 83.18,48.09 81.91,49.37 | 78.73,49.37 81.91,49.37 | 81.91,49.37 92.07,49.37 | R13.1 106.04,17.62 104.77,17.62 R2.2 103.5,17.62 102.23,18.89 92.07,18.89 | R153.1 95.88,17.62 94.61,17.62 R151.2 93.34,17.62 92.07,18.89 | R139.2 74.29,17.62 75.56,17.62 R141.1 76.83,17.62 78.1,18.89 81.91,18.89 | R8.1 85.72,17.62 84.45,17.62 R4.2 83.18,17.62 81.91,18.89 | 92.07,18.89 81.91,18.89 | R147.2 74.29,32.86 75.56,32.86 R149.1 76.83,32.86 78.1,34.12 81.91,34.12 83.18,32.86 R159.2 84.45,32.86 85.72,32.86 R161.1 86.99,32.86 89.53,35.4 92.7,35.4 95.25,32.86 | 95.25,32.86 95.88,32.86 R145.1 97.15,32.86 98.42,34.12 102.23,34.12 103.5,32.86 R155.2 104.77,32.86 106.04,32.86 R157.1 | 95.25,32.86 94.61,32.86 R143.2 | R225.1 106.04,91.27 104.77,91.27 R223.2 103.5,91.27 102.23,92.54 92.07,92.54 | R209.1 95.88,91.27 94.61,91.27 R207.2 93.34,91.27 92.07,92.54 | R203.2 74.29,91.27 75.56,91.27 R205.1 76.83,91.27 78.1,92.54 81.91,92.54 83.18,91.27 R219.2 84.45,91.27 85.72,91.27 R221.1 86.99,91.27 88.26,92.54 92.07,92.54 | R195.2 74.29,76.03 75.56,76.03 R197.1 76.83,76.03 78.1,77.3 81.91,77.3 83.18,76.03 R211.2 84.45,76.03 85.72,76.03 R213.1 86.99,76.03 88.26,74.77 93.34,74.77 | R193.1 106.04,63.34 104.77,63.34 R191.2 103.5,63.34 102.23,64.6 92.7,64.6 | R177.1 95.88,63.34 94.61,63.34 R175.2 93.34,63.34 92.7,63.97
  Top 0.254: R171.2 74.29,63.34 75.56,63.34 R173.1 76.2,63.97 77.47,65.24 82.55,65.24 83.18,64.6 | R189.1 85.72,63.34 84.45,63.34 R187.2 83.81,63.97 83.18,64.6 | 92.7,63.97 92.07,64.6 83.18,64.6 | 93.34,74.77 92.7,74.13 92.7,64.6 | 93.34,74.77 93.98,75.4 R199.2 94.61,76.03 95.88,76.03 R201.1 97.15,76.03 98.42,77.3 102.23,77.3 103.5,76.03 R215.2 | 92.7,64.6 92.7,63.97 | R239.2 94.61,121.75 95.88,121.75 R241.1 | R235.2 74.29,121.75 75.56,121.75 R237.1 76.83,121.75 78.1,123.02 81.91,123.02 83.18,121.75 R251.2 | R251.2 84.45,121.75 85.72,121.75 R253.1 | R249.1 106.04,106.52 104.77,106.52 R247.2 103.5,106.52 102.23,107.78 92.07,107.78 | R233.1 95.88,106.52 94.61,106.52 R231.2 93.34,106.52 92.07,107.78 | R227.2 74.29,106.52 75.56,106.52 R229.1 76.83,106.52 78.1,107.78 81.91,107.78 | R245.1 85.72,106.52 84.45,106.52 R243.2 83.18,106.52 81.91,107.78 | 82.55,107.78 81.91,107.78 | 82.55,107.78 92.07,107.78 | 82.55,107.78 82.55,119.85 83.81,121.12 R251.2 | R255.2 104.77,121.75 106.04,121.75 R257.1 | v78.73,58.26 78.73,49.37
  Bottom 0.254: R153.1 96.52,18.25 96.52,23.33 100.33,27.14 100.33,28.41 100.96,29.05 102.23,29.05 102.87,29.68 102.87,30.95 104.14,32.22 R155.2 | R165.1 76.83,48.09 80.64,44.29 81.91,44.29 82.55,43.65 82.55,34.76 83.81,33.49 R159.2 | R215.2 104.77,76.03 106.04,76.03 R217.1 | R195.2 73.66,76.67 71.75,78.57 71.75,90 73.02,91.27 R203.2 73.66,91.91 73.66,94.45 78.73,99.53 78.73,103.34 76.2,105.88 R229.1 | R239.2 93.34,121.75 92.07,123.02 88.26,123.02 86.99,121.75 R253.1 | IC10.OUT 179.7,147.79 144.14,147.79 142.87,149.06 116.84,149.06 107.95,140.17 107.95,123.66 106.68,122.39 R257.1 | R241.1 97.15,121.75 98.42,123.02 102.23,123.02 103.5,121.75 R255.2 | v78.73,58.26 78.73,60.16 76.2,62.7 R173.1
A1  (via drill 0.61)
  Top 0.254: 31.75,4.28 34.28,1.74 77.47,1.74 v81.91,6.18 86.99,11.27 Q4.D | 31.75,4.28 26.03,10 R3.1 | v114.3,142.71 93.98,142.71 v88.9,147.79 | v44.45,149.7 19.68,149.7 7.62,137.63 7.62,13.17 16.51,4.28 31.75,4.28 | v130.81,8.73 126.36,8.73 v121.28,13.81 | v101.59,3.01 85.09,3.01 v83.18,4.92
  Bottom 0.254: Q1.D 154.94,14.44 153.03,12.54 151.76,12.54 150.49,13.81 Q2.D 149.22,13.81 146.68,13.81 146.05,13.17 146.05,9.36 145.41,8.73 v130.81,8.73 | v114.3,142.71 111.76,140.17 SIDE1.10 | v88.9,147.79 50.16,147.79 48.25,149.7 v44.45,149.7 | v121.28,13.81 118.74,11.27 109.85,11.27 v101.59,3.01 | v81.91,6.18 v83.18,4.92
A2
  Top 0.254: A2.1 38.73,139.53 45.08,139.53 SIDE2.2
B1  (via drill 0.61)
  Top 0.254: Q5.D 76.83,11.27 69.84,11.27 58.41,22.7 40,22.7 33.02,15.71 R16.1 | Q35.D 134.62,14.44 132.71,12.54 131.44,12.54 130.17,13.81 Q36.D 128.9,13.81 126.36,16.35 118.74,16.35 117.47,15.08 121.92,10.63 | v119.38,145.25 115.56,141.44 109.22,141.44 107.31,139.53 SIDE1.6 | v193.67,114.13 v193.67,26.51 | v172.08,10 168.27,6.18 126.36,6.18 121.92,10.63 | v115.56,4.28 v85.09,4.28 | 121.92,10.63 v121.28,10
  Bottom 0.254: v119.38,145.25 162.56,145.25 v193.67,114.13 | v193.67,26.51 192.4,26.51 175.89,10 v172.08,10 | v85.09,4.28 78.1,11.27 Q5.D | v121.28,10 v115.56,4.28
B2
  Top 0.254: SIDE2.4 48.25,140.17 48.25,145.89 B2.1
C1  (via drill 0.61)
  Top 0.254: SIDE1.1 102.23,137 103.5,137 SIDE1.3 104.77,137 106.04,137 SIDE1.5 107.31,137 108.58,137 SIDE1.7 109.85,137 111.12,137 SIDE1.9 112.39,137 113.66,137 SIDE1.11 114.93,137 116.2,137 SIDE1.13 117.47,137 118.74,137 SIDE1.15 120.01,137 121.28,137 SIDE1.17 122.55,137 123.82,137 SIDE1.19 125.09,137 126.36,137 SIDE1.21 127.63,137 128.9,137 SIDE1.23 130.17,137 131.44,137 SIDE1.25 132.71,137 133.98,137 SIDE1.27 135.25,137 136.52,137 SIDE1.29 137.79,137 139.06,137 SIDE1.31 140.33,137 141.6,137 SIDE1.33 | Q38.D 150.49,29.05 151.76,27.78 153.03,27.78 154.94,29.68 Q37.D | v90.8,20.16 67.31,20.16 66.04,18.89 64.77,18.89 60.32,23.33 37.46,23.33 32.38,28.41 32.38,31.59 31.11,32.86 R20.1 | v145.41,36.03 135.88,36.03 v135.25,36.66 | v125.73,35.4 125.73,29.68 123.82,27.78 123.82,25.23 115.56,16.98 115.56,9.36 v114.93,8.73 113.66,7.46 92.07,7.46 90.17,9.36 v90.17,16.35 | v167,130.65 168.27,130.65 168.91,131.28 170.18,131.28 193.03,108.42 193.03,27.14 171.44,5.55 121.92,5.55 v118.74,8.73
  Bottom 0.254: Q6.D 97.15,26.51 v90.8,20.16 90.17,19.52 v90.17,16.35 | v145.41,36.03 147.95,33.49 147.95,32.86 149.86,30.95 149.86,29.68 Q38.D | v135.25,36.66 133.98,35.4 v125.73,35.4 | v167,130.65 160.65,137 142.87,137 SIDE1.33 | v118.74,8.73 v114.93,8.73
C2
  Top 0.254: C2.1 38.73,135.09 43.17,135.09 45.08,137 SIDE2.1 46.35,137 47.62,137 SIDE2.3 48.89,137 50.16,137 SIDE2.5 51.43,137 52.7,137 SIDE2.7 53.97,137 55.24,137 SIDE2.9 56.51,137 57.78,137 SIDE2.11 59.05,137 60.32,137 SIDE2.13 61.59,137 62.86,137 SIDE2.15 64.13,137 65.4,137 SIDE2.17 66.67,137 67.94,137 SIDE2.19 69.21,137 70.48,137 SIDE2.21 71.75,137 73.02,137 SIDE2.23 74.29,137 75.56,137 SIDE2.25 76.83,137 78.1,137 SIDE2.27 79.37,137 80.64,137 SIDE2.29 81.91,137 83.18,137 SIDE2.31 84.45,137 85.72,137 SIDE2.33
D1  (via drill 0.61)
  Top 0.254: 66.67,23.96 69.21,26.51 76.83,26.51 Q7.D | 66.67,23.96 64.77,23.96 v56.51,32.22 | v116.84,147.79 110.48,147.79 108.58,149.7 45.71,149.7 41.9,145.89 17.14,145.89 8.25,137 8.25,41.74 v14.6,35.4 | v22.22,35.4 24.76,32.86 R24.1 | v120.65,18.25 129.53,27.14 129.53,28.41 Q40.D | v102.87,26.51 102.87,24.6 102.23,23.96 66.67,23.96
  Bottom 0.254: Q40.D 130.17,29.05 131.44,27.78 132.71,27.78 134.62,29.68 Q39.D | v56.51,32.22 54.6,34.12 27.3,34.12 26.03,32.86 R24.1 | v116.84,147.79 109.22,140.17 SIDE1.8 | v14.6,35.4 v22.22,35.4 | v120.65,18.25 120.65,14.44 119.38,13.17 115.56,13.17 112.39,16.35 100.96,16.35 100.33,16.98 100.33,25.87 100.96,26.51 v102.87,26.51
D2  (via drill 0.61)
  Top 0.254: Q68.D 139.69,71.59 139.69,70.32 140.97,69.05 140.97,67.78 141.6,67.14 145.41,67.14 146.05,67.78 146.05,69.05 145.41,69.68 144.14,69.68 143.5,70.32 143.5,71.59 144.78,72.86 Q67.D | 103.5,78.57 105.41,76.67 105.41,75.4 104.77,74.77 100.96,74.77 99.06,72.86 99.06,71.59 97.79,70.32 Q20.D | 103.5,78.57 102.23,79.84 73.02,79.84 72.39,79.21 v70.48,79.21 38.09,79.21 33.02,74.13 R80.1 | v62.22,138.27 52.7,138.27 51.43,139.53 SIDE2.6 | v63.49,126.83 62.22,125.56 66.67,121.12 66.67,112.23 67.94,110.96 67.94,100.16 69.21,98.89 v69.21,90 | v117.47,92.54 v123.82,92.54 | v109.85,86.19 109.85,84.92 103.5,78.57
  Bottom 0.254: v62.22,138.27 62.22,128.11 v63.49,126.83 | v69.21,90 69.21,88.73 70.48,87.46 v70.48,79.21 | v123.82,92.54 127,89.37 127,84.29 128.9,82.38 130.81,82.38 137.16,76.03 137.16,75.4 139.69,72.86 Q68.D | v117.47,92.54 112.39,87.46 111.12,87.46 v109.85,86.19
E1  (via drill 0.61)
  Top 0.254: Q42.D 160.65,13.81 161.92,12.54 163.19,12.54 165.09,14.44 Q41.D 165.09,15.71 165.09,16.98 162.56,19.52 v130.81,19.52 | v125.09,19.52 v128.27,19.52
  Bottom 0.254: 97.79,1.74 57.14,1.74 48.89,10 R28.1 | 97.79,1.74 107.31,11.27 Q3.D | 132.08,1.74 97.79,1.74 | 132.08,1.74 173.99,1.74 197.48,25.23 197.48,109.05 161.92,144.62 120.01,144.62 114.93,139.53 SIDE1.12 | v128.27,19.52 v130.81,19.52 | v125.09,19.52 125.09,8.73 132.08,1.74
E2  (via drill 0.61)
  Top 0.254: Q21.D 76.83,84.92 67.94,84.92 64.77,81.75 v57.78,81.75 37.46,81.75 33.02,86.19 33.02,90 31.75,91.27 31.11,91.27 R84.1 | v19.05,132.55 19.05,131.28 10.15,122.39 10.15,96.99 v13.96,93.18 | v130.81,79.84 130.81,84.29 129.53,85.56 129.53,86.83 Q70.D | v126.36,77.3 126.36,72.22 v122.55,68.41 | v98.42,54.45 v107.31,54.45 | v62.22,66.51 v62.22,60.8 | v57.78,76.03 v57.78,70.95
  Bottom 0.254: Q70.D 130.17,87.46 131.44,86.19 132.71,86.19 134.62,88.1 Q69.D | v19.05,132.55 22.86,136.36 37.46,136.36 39.36,138.27 51.43,138.27 52.7,139.53 SIDE2.8 | v13.96,93.18 27.94,93.18 29.84,91.27 R84.1 | v130.81,79.84 130.81,79.21 131.44,78.57 130.17,77.3 v126.36,77.3 | v122.55,68.41 122.55,67.14 112.39,56.98 109.85,56.98 v107.31,54.45 | v98.42,54.45 96.52,52.54 74.93,52.54 74.29,51.91 71.12,51.91 v62.22,60.8 | v57.78,70.95 v62.22,66.51 | v57.78,81.75 v57.78,76.03
F1  (via drill 0.61)
  Top 0.254: v127.63,110.32 v127.63,27.78 116.2,16.35 116.2,8.73 113.03,5.55 v99.06,5.55
  Bottom 0.254: 95.25,9.36 88.26,2.38 69.21,2.38 56.51,15.08 R32.1 | 95.25,9.36 97.15,11.27 Q8.D | Q43.D 144.78,14.44 142.87,12.54 141.6,12.54 140.33,13.81 Q44.D 139.69,14.44 139.69,15.08 136.52,18.25 134.62,18.25 127.63,25.23 v127.63,27.78 | v127.63,110.32 118.11,119.85 118.11,137.63 116.84,138.9 SIDE1.14 | v99.06,5.55 95.25,9.36
F2  (via drill 0.61)
  Top 0.254: v100.33,90 100.33,88.1 97.79,85.56 Q22.D | v117.47,93.81 118.74,95.08 122.55,95.08 v123.82,93.81 | v19.05,96.99 24.76,91.27 R88.1 | v16.51,109.05 16.51,110.32 11.42,115.4 11.42,122.39 v19.05,130.01 | v90.17,105.24 v90.17,100.16 | v60.95,120.48 60.95,123.02 v61.59,123.66
  Bottom 0.254: v100.33,90 100.33,91.91 101.59,93.18 | 101.59,93.18 102.87,94.45 116.84,94.45 v117.47,93.81 | v123.82,93.81 134.62,93.81 139.69,88.73 139.69,88.1 Q72.D 140.33,87.46 141.6,86.19 142.87,86.19 144.78,88.1 Q71.D | v19.05,96.99 17.78,96.99 16.51,98.26 v16.51,109.05 | v19.05,130.01 48.25,130.01 53.34,135.09 | 53.34,135.09 54.6,136.36 54.6,137.63 55.88,138.9 SIDE2.10 | 101.59,93.18 94.61,100.16 v90.17,100.16 | v90.17,105.24 90.17,107.15 86.99,110.32 79.37,110.32 74.29,115.4 73.02,115.4 69.21,119.21 69.21,122.39 67.94,123.66 66.67,123.66 63.49,120.48 v60.95,120.48 | v61.59,123.66 62.86,124.93 57.14,130.65 57.14,131.28 53.34,135.09
GND  (via drill 0.61)
  Top 0.254: 157.47,149.06 168.91,149.06 | 168.91,149.06 183.51,149.06 184.78,147.79 IC10.GND | 157.47,149.06 141.6,149.06 140.33,147.79 T1.2 | 147.31,44.92 145.41,43.02 D90.A | 147.31,44.92 Q57.S | 147.31,44.92 149.86,42.38 149.86,41.11 R276.2 | 147.31,44.92 Q57.S | D83.A 149.86,47.46 147.95,45.55 Q57.S | Q59.S 167.63,44.92 165.73,43.02 D92.A 164.46,43.02 163.83,42.38 160.02,42.38 | 160.02,42.38 160.02,41.11 R284.2 | 160.02,42.38 157.47,44.92 Q51.S 158.11,45.55 160.02,47.46 D91.A | 147.31,29.68 145.41,27.78 D80.A | 147.31,29.68 Q47.S | 149.86,27.14 149.86,25.87 R262.2 | 147.31,29.68 149.86,27.14 | 147.31,29.68 Q47.S | D69.A 149.86,32.22 147.95,30.32 Q47.S | Q45.S 167,30.32 165.09,28.41 D78.A 164.46,27.78 163.83,27.14 160.02,27.14 | 157.47,29.68 155.57,27.78 D70.A 154.94,27.14 149.86,27.14 | 157.47,29.68 Q37.S | 160.02,27.14 160.02,25.87 R270.2 | 157.47,29.68 160.02,27.14 | 157.47,29.68 Q37.S | D77.A 160.02,32.22 158.11,30.32 Q37.S | 147.31,14.44 145.41,12.54 D76.A | 147.31,14.44 Q43.S | 147.31,14.44 149.86,11.9 149.86,10.63 R11.2 | 147.31,14.44 Q43.S | D3.A 149.86,16.98 147.95,15.08 Q43.S | Q41.S 167.63,14.44 165.73,12.54 D74.A 164.46,12.54 163.83,11.9 160.02,11.9 | 157.47,14.44 155.57,12.54 D6.A | 157.47,14.44 Q1.S 157.47,14.44 | 160.02,11.9 160.02,10.63 R266.2 | 157.47,14.44 158.11,13.81 | 158.11,13.81 160.02,11.9 | 158.11,13.81 160.02,15.71 160.02,16.98 D73.A | D71.A 129.53,33.49 129.53,39.84 R274.2 | 137.16,44.92 135.25,43.02 D82.A | Q49.S 137.16,44.92 | Q49.S 137.79,45.55 139.69,47.46 D89.A 139.06,48.09 137.79,48.09 130.17,55.72 R278.2 129.53,55.08 129.53,48.73 D81.A | R260.2 130.17,10 132.08,11.9 134.62,11.9 D68.A 135.25,12.54 137.16,14.44
  Top 0.254: Q35.S 137.16,14.44 | 137.16,14.44 139.69,11.9 139.69,10.63 R268.2 | Q35.S 137.16,14.44 | D75.A 139.69,16.98 137.79,15.08 Q35.S | D67.A 129.53,18.25 129.53,24.6 R264.2 | D72.A 135.25,27.78 137.16,29.68 Q39.S 137.79,30.32 139.69,32.22 D79.A | 137.16,44.92 139.69,42.38 139.69,41.11 R282.2 | Q49.S 137.16,44.92 | 147.31,60.16 145.41,58.26 D94.A | Q61.S 147.31,60.16 | 147.31,60.16 149.86,57.62 149.86,56.35 R280.2 | Q61.S 147.31,60.16 | Q61.S 147.95,60.8 149.86,62.7 D87.A 149.86,63.97 149.86,65.24 | 149.86,65.24 149.86,67.78 R298.2 | 157.47,72.86 155.57,70.95 D106.A | 157.47,72.86 Q73.S 157.47,72.86 | Q75.S 167.63,72.86 165.73,70.95 D108.A 164.46,70.95 163.19,69.68 161.92,69.68 161.28,69.05 | Q63.S 167.63,60.16 165.73,58.26 D96.A 164.46,58.26 163.83,57.62 160.02,57.62 | 157.47,60.16 155.57,58.26 D88.A | Q55.S 157.47,60.16 | 160.02,57.62 160.02,56.35 R288.2 | 157.47,60.16 160.02,57.62 | Q55.S 157.47,60.16 | Q55.S 158.11,60.8 160.02,62.7 D95.A 160.02,63.97 160.02,65.24 | 160.02,65.24 160.02,67.78 R300.2 160.65,68.41 161.28,69.05 | 161.28,69.05 157.47,72.86 | 149.86,65.24 160.02,65.24 | D98.A 135.25,70.95 137.16,72.86 Q65.S 137.79,73.49 139.69,75.4 D99.A | D100.A 145.41,70.95 147.31,72.86 Q67.S | 129.53,65.24 129.53,67.78 R290.2 | 129.53,65.24 129.53,63.97 D85.A | 137.16,60.16 135.25,58.26 D86.A | Q53.S 137.16,60.16 | 137.16,60.16 139.69,57.62 139.69,56.35 R286.2 | Q53.S 137.16,60.16 | Q53.S 137.79,60.8 139.69,62.7 D93.A 139.69,63.97 139.69,65.24 | 139.69,65.24 139.69,67.78 R292.2 | 139.69,65.24 129.53,65.24 | 147.31,88.1 149.86,85.56 149.86,84.29 R302.2 | Q71.S 147.31,88.1 | 147.31,88.1 145.41,86.19 D104.A
  Top 0.254: Q71.S 147.31,88.1 | D109.A 149.86,90.64 147.95,88.73 Q71.S | Q79.S 167.63,88.1 165.73,86.19 D112.A 164.46,86.19 163.83,85.56 160.02,85.56 | 157.47,88.1 155.57,86.19 D110.A | 157.47,88.1 Q77.S | 160.02,85.56 160.02,84.29 R304.2 | 157.47,88.1 160.02,85.56 | 157.47,88.1 Q77.S | D111.A 160.02,90.64 158.11,88.73 Q77.S | D97.A 129.53,76.67 129.53,77.94 128.9,78.57 128.9,83.65 R294.2 | D102.A 135.25,86.19 137.16,88.1 Q69.S 137.79,88.73 139.69,90.64 D103.A | D118.A 135.25,116.67 137.16,118.58 Q85.S 137.79,119.21 139.69,121.12 D125.A | D101.A 129.53,91.91 129.53,98.26 R306.2 | 137.16,103.34 135.25,101.43 D114.A | Q81.S 137.16,103.34 | D113.A 130.17,106.52 131.44,107.78 137.79,107.78 139.06,106.52 D115.A 139.69,105.88 137.79,103.97 Q81.S | Q95.S 167.63,118.58 165.73,116.67 D128.A 164.46,116.67 163.83,116.04 160.02,116.04 | 157.47,118.58 155.57,116.67 D120.A | 157.47,118.58 Q87.S | 160.02,116.04 160.02,114.77 R320.2 | 157.47,118.58 160.02,116.04 | 157.47,118.58 Q87.S | Q87.S 158.11,119.21 160.02,121.12 D127.A 160.02,122.39 157.47,124.93 157.47,149.06 | Q91.S 167.63,103.34 165.73,101.43 D124.A 164.46,101.43 163.83,100.8 160.02,100.8 | 157.47,103.34 155.57,101.43 D122.A | 157.47,103.34 Q89.S | 160.02,100.8 160.02,99.53 R316.2 | 157.47,103.34 160.02,100.8 | 157.47,103.34 Q89.S | D123.A 160.02,105.88 158.11,103.97 Q89.S | D126.A 145.41,116.67 147.31,118.58 Q93.S 147.95,119.21 149.86,121.12 D119.A | 147.31,103.34 145.41,101.43 D116.A | Q83.S 147.31,103.34 | 147.31,103.34 149.86,100.8 149.86,99.53 R314.2 | Q83.S 147.31,103.34 | D121.A 149.86,105.88 147.95,103.97 Q83.S | 137.16,103.34 139.69,100.8 139.69,99.53 R308.2
  Top 0.254: Q81.S 137.16,103.34 | D44.A 101.59,43.65 101.59,44.92 R170.2 | D43.A 81.28,43.65 81.28,44.92 R166.2 | D47.A 91.44,43.65 91.44,44.92 R182.2 | D5.A 101.59,28.41 101.59,29.68 R146.2 | D8.A 81.28,28.41 81.28,29.68 R150.2 | D42.A 91.44,28.41 91.44,29.68 R162.2 | D40.A 101.59,13.17 101.59,14.44 R154.2 | R142.2 81.28,14.44 81.28,13.17 D4.A 81.28,11.9 82.55,10.63 82.55,9.36 81.91,8.73 v59.05,8.73 | D1.A 91.44,13.17 91.44,14.44 R9.2 | D7.A 111.76,13.17 111.76,14.44 R14.2 111.76,15.71 113.03,16.98 113.03,25.87 111.76,27.14 D41.A 111.76,28.41 111.76,29.68 R158.2 111.76,30.95 113.66,32.86 113.66,40.48 111.76,42.38 D48.A 111.76,43.65 111.76,44.92 R186.2 111.76,46.19 113.03,47.46 113.03,56.35 111.76,57.62 D50.A 111.76,58.89 111.76,60.16 R194.2 111.76,61.43 113.03,62.7 113.03,65.24 110.48,67.78 110.48,69.05 111.76,70.32 D56.A 111.76,71.59 111.76,72.86 R218.2 111.76,74.13 113.03,75.4 113.03,84.29 111.76,85.56 D58.A 111.76,86.83 111.76,88.1 R226.2 | D46.A 101.59,58.89 101.59,60.16 R178.2 | D49.A 91.44,58.89 91.44,60.16 R190.2 | D45.A 81.28,58.89 81.28,60.16 R174.2 | D51.A 81.28,71.59 81.28,72.86 R198.2 81.91,73.49 83.18,74.77 86.99,74.77 90.8,70.95 D55.A 91.44,71.59 91.44,72.86 R214.2 | D52.A 101.59,71.59 101.59,72.86 R202.2 | R258.2 111.76,118.58 111.76,117.31 D66.A 111.76,116.04 110.48,114.77 v110.48,107.78 | D62.A 101.59,117.31 101.59,118.58 R242.2 | D61.A 81.28,117.31 81.28,118.58 R238.2 | D65.A 91.44,117.31 91.44,118.58 R254.2 | D54.A 101.59,86.83 101.59,88.1 R210.2 | D53.A 81.28,86.83 81.28,88.1 R206.2 | D57.A 91.44,86.83 91.44,88.1 R222.2 | D59.A 81.28,102.07 81.28,103.34 R230.2
  Top 0.254: D63.A 91.44,102.07 91.44,103.34 R246.2 | D60.A 101.59,102.07 101.59,103.34 R234.2 | D64.A 111.76,102.07 111.76,103.34 R250.2 | D2.A 17.14,10 15.87,11.27 14.6,11.27 13.33,10 D9.A 12.69,10.63 10.79,12.54 10.79,30.32 12.69,32.22 D10.A 13.33,32.86 15.23,34.76 | 48.25,11.9 48.89,11.9 49.52,11.27 52.7,11.27 53.34,11.9 R31.1 | 48.25,11.9 R27.1 48.25,11.9 | 31.11,11.27 32.38,10 34.92,10 D13.A | 31.11,11.27 30.48,11.9 R15.1 | 48.25,11.9 46.35,10 45.08,10 43.81,8.73 42.54,8.73 41.27,10 D12.A | 31.11,11.27 26.67,11.27 26.03,11.9 25.39,11.9 R1.1 | 16.51,36.03 17.78,37.3 17.78,39.84 D16.A | 15.23,34.76 16.51,36.03 | 15.23,34.76 16.51,33.49 | 16.51,33.49 17.14,32.86 D11.A 18.41,32.86 19.68,31.59 20.95,31.59 | 20.95,31.59 22.22,30.32 R23.1 | 20.95,31.59 26.67,31.59 27.3,30.95 27.3,30.32 R19.1 | 16.51,36.03 12.69,39.84 D17.A 12.69,41.11 10.79,43.02 10.79,60.8 12.69,62.7 D18.A 13.33,63.34 17.78,67.78 | 16.51,33.49 25.39,42.38 | 25.39,42.38 R43.1 25.39,42.38 | R63.1 53.34,42.38 52.7,41.74 50.16,41.74 48.89,40.48 R59.1 47.62,40.48 45.08,40.48 43.81,39.2 38.73,39.2 | 35.55,36.03 35.55,39.84 D21.A | 35.55,36.03 35.55,33.49 D14.A 36.19,32.86 37.46,31.59 38.73,31.59 | 38.73,31.59 40,32.86 D15.A | 35.55,36.03 38.73,39.2 | 38.73,39.2 40,40.48 D20.A | 38.73,31.59 43.81,31.59 45.08,30.32 R39.1 45.71,29.68 46.35,29.05 49.52,29.05 50.16,29.68 50.79,29.68 R35.1 | 25.39,42.38 26.03,42.38 26.67,41.74 29.84,41.74 30.48,42.38 R47.1 | D34.A 13.33,121.75 14.6,123.02 15.87,123.02 17.14,121.75 D35.A 18.41,121.75 19.68,120.48 20.95,120.48 22.22,119.21 R119.1 22.86,118.58 23.49,117.94 26.67,117.94 27.3,118.58 27.94,118.58 R115.1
